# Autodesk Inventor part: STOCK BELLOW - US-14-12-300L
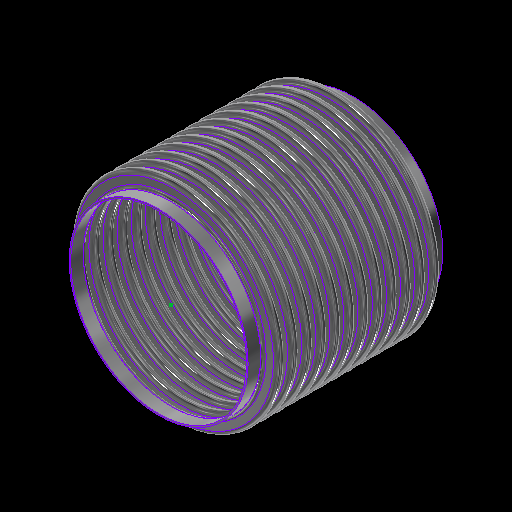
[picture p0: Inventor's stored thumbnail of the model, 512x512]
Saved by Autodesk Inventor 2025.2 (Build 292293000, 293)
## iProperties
Category: 16 GA (0.060 THICK)
RuleStatus: InUse
Created: 2024-01
Part Number: STOCK BELLOW - US-14-12-300L
Project: =STOCK BELLOWS: <Stock Number><SFILL>
Material: ASTM A240-304
Description: =STOCK BELLOWS: <Stock Number>, <SID_> I.D., <SOD_> O.D., <SPLY_> PLY, <Category>, <SNET_CONS> CONS.<PITCH_><STANGENT_> TANGENT<SFILL>
Document SubType Name: Sheet Metal
Designer: GS
Stock Number: U.S-14-12-300L
Surface Area: 22879.5 cm^2
Volume: 3455.43 cm^3
Sheet Metal Rule: Default
Appearance: STAINLESS STEEL
Mass: 27841.4 g
Density: 8.05729 g/cm^3
THK: 0.036
ID: 3.500
OD: 4.250
CONS_: 2
PITCH: 0.500
TANGENT: 0.500
BELLOWS_UPSET: 0.000
d79: 1.000
d82: 1.000
d83: 26.000
d84: 24.000
d174: 8
d214: 8
STHK_: 0.060
SID_: 14.000
SOD_: 16.500
SPITCH_: 1.125
STANGENT__: 1.000
SBELLOWS_UPSET_: 0.000
SDIFF_TAN: 1.000
d252: 2
d275: 2
d287: 0.050
d289: 0.500
d290: 0.000
SOD_NECK: 14 1/4
PLY: 1
PSET: 4.178
PBAR: 1.035
COUNTER: 1.500
NET_TUBE: 3.071
CONS: 2
S_CONS: 0
NET_CONS: 2
ID_M: 88.90 mm
OD_M: 107.95 mm
THK_M: 0.91 mm
ID_U: 3.500 in
OD_U: 4.250 in
THK_U: 0.036 in
TANGENT2: 0.500
TAN_TO_TAN: 1.000 in
d80: 2.571
d81: 10
SID: 2.375
SCONS_: 12
SPITCH: 0.250
STANGENT_: 1.000
SBELLOWS_UPSET: 0.000
SNET_CONS: 12
SS_CONS: 0
SCONS: 8
d190: 8
d191: 1
d192: 1
d193: 8
d194: 0
SIZE: 14.00
PRESSURE: 300
d230: 8
STANGENT: 4.000
SPLY_: 2
d233: 8
d234: 0
d263: 2
d265: 1
d268: 2
d269: 0
d286: 2
d288: 1
d291: 2
d292: 0
SREROLL: 0.750
BLETP: 1.000 ul
PRES_Copy: 85
MATTABLE: 20 GA (0.036 THICK)
PART_NUMBER: U.S-14-12-300L
PITCH_: =, <SPITCH_> PITCH,
CFILL: .
SFILL: .
MESH: ,
COMP: 2.32
EXT: 1.16
LAT: 0.68
ANG: 573
ASR: 5457
LSR: 10445
ANSR: 2769
PRES: 300
COMPM: 23.2
EXTM: 11.6
LATM: 6.80
ASRM: 955.684
PRESM: 20.684
LSRM: 1829.233
ANSRM: 484.935
TEMPMIN: 20
TEMPMAX: 800
TEMPMINM: -7
TEMPMAXM: 427
WEIGHTM: 27.841
WEIGHT: 61.380
Author: GS
Keywords: 20 GA (0.036 THICK)
Comments: =STOCK BELLOW - <STOCK NUMBER>
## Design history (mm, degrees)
sketch "Sketch2"
  geometry: L1 (0, -177.245)-(0, 562.856) reference; L2 (45.364, 0)-(44.45, 0); L3 (48.082, -2.718)-(50.343, -2.718); L4 (48.082, -3.632)-(50.343, -3.632); L5 (50.343, -9.982)-(48.082, -9.982); L6 (50.343, -9.068)-(48.082, -9.068); L7 (45.364, -12.7)-(44.45, -12.7); L8 (48.082, 0)-(48.082, -12.7); L9 (50.343, -6.35)-(53.975, -6.35); L10 (44.45, 0)-(44.45, -12.7); L11 (20.376, 102.841)-(20.376, 101.926); L12 (58.262, 457.127)-(58.262, 349.177); L13 (58.262, 444.427)-(58.262, 336.477); L14 (93.133, -58.817)-(93.133, -71.517); L15 (118.746, -66.401)-(118.746, -66.401); L16 (50.343, -9.068)-(50.343, -9.982); L17 (48.082, -9.068)-(48.082, -9.982); L18 (48.082, -9.525)-(50.343, -9.525); L19 (53.975, 0)-(53.975, -12.7); L20 (-50.343, -9.068)-(-50.343, -9.982); L21 (-50.343, -2.718)-(-48.082, -2.718); L22 (-50.343, -3.632)-(-48.082, -3.632); L23 (-48.082, -9.068)-(-50.343, -9.068); L24 (-50.343, -9.525)-(-48.082, -9.525); L25 (-48.082, -9.982)-(-50.343, -9.982); L26 (-48.082, -9.068)-(-48.082, -9.982); L27 (-44.45, 0.653)-(-44.45, -12.047); L28 (-48.082, -6.35)-(-44.45, -6.35); L29 (-50.343, 0.653)-(-50.343, -12.7); L30 (-53.061, 0)-(-53.975, 0); L31 (-53.975, 0)-(-53.975, -12.7); L32 (-53.061, -12.7)-(-53.975, -12.7); A1 r 2.718 centre (48.082, 0) between (45.364, 0) and (48.082, -2.718); A2 r 3.632 centre (48.082, 0) between (44.45, 0) and (48.082, -3.632); A3 r 3.632 centre (50.343, -6.35) between (50.343, -9.982) and (50.343, -2.718); A4 r 2.718 centre (50.343, -6.35) between (50.343, -9.068) and (50.343, -3.632); A5 r 2.718 centre (48.082, -12.7) between (48.082, -9.982) and (45.364, -12.7); A6 r 3.632 centre (48.082, -12.7) between (48.082, -9.068) and (44.45, -12.7); A7 r 3.175 centre (50.343, -6.35) between (50.343, -9.525) and (53.518, -6.35); A8 r 3.175 centre (48.082, -12.7) between (48.082, -9.525) and (44.907, -12.7); A9 r 2.718 centre (-50.343, -12.7) between (-50.343, -9.982) and (-53.061, -12.7); A10 r 2.718 centre (-48.082, -6.35) between (-48.082, -9.068) and (-48.082, -3.632); A11 r 3.175 centre (-48.082, -6.35) between (-48.082, -9.525) and (-44.907, -6.35); A12 r 3.632 centre (-48.082, -6.35) between (-48.082, -9.982) and (-48.082, -2.718); A13 r 3.175 centre (-50.343, -12.7) between (-50.343, -9.525) and (-53.518, -12.7); A14 r 3.632 centre (-50.343, -12.7) between (-50.343, -9.068) and (-53.975, -12.7); A15 r 2.718 centre (-50.343, 0) between (-53.061, 0) and (-50.343, -2.718); A16 r 3.632 centre (-50.343, 0) between (-53.975, 0) and (-50.343, -3.632); 10 further points
  constraints: 62 end point, 38 point on circle, 20 tangent, 16 centre point, 12 parallel, 9 midpoint, 7 vertical, 6 coincident, 6 concentric, 6 point on line, 4 equal radius, 4 perpendicular, 3 horizontal, 1 collinear, 1 horizontal alignment, 10 other
  dimensions: "THK" = 0.9144 distance of L11.start L11.end; "ID" = 88.9 distance of L11.end point (20.376, 13.026); "OD" = 107.95 distance of L12.start L12.end; "PITCH" = 12.7 distance of L12.start L13.start; "TANGENT" = 12.7 distance of L14.start L14.end; "BELLOWS_UPSET" = 0 distance of L15.start L15.end; "d43" = 88.9 diameter of L10 L1 (= ID); "d44" = 107.95 diameter of L9.end L1 (= OD); "d45" = 0.9144 distance between parallel lines of L5 L6 (computed from THK, PLY); "d46" = 3.6322 radius of A3 (computed from PITCH, THK, PLY); "UPSET_PITCH" = 12.7 distance of L2.end L7.end (derived); "SIDEWALL_ANGLE" = 360 deg dimension on L3 L9 (derived); "CON_GAP" = 5.4356 distance of point (48.082, -9.068) point (48.082, -3.632) (derived); "TAN1" = 4.98728 dimension on A8 (derived); "TAN2" = 4.98728 dimension on A7 (derived); "LEG1" = 2.2606 distance of L18.start L18.end (derived); "d278" = 0.9144 distance between parallel lines of L25 L23 (derived); "d279" = 3.6322 radius of A12 (derived); "d280" = 12.7 distance of L30.end L31.end (derived); "d281" = 360 deg dimension on L21 L28 (derived); "d282" = 5.4356 distance of point (-50.343, -9.068) point (-50.343, -3.632) (derived); "d283" = 4.98728 dimension on A13 (derived); "d284" = 4.98728 dimension on A11 (derived); "d285" = 2.2606 distance of L24.start L24.end (derived); "d293" = 88.9 diameter of L27 L1 (derived); "d294" = 107.95 diameter of L31 L1 (derived)
  node "Sketch Rectangular Pattern1" dims "d31" = 25.4, "ID" = 88.9
  node "Sketch Rectangular Pattern2" dims "d39" = 25.4, "PITCH" = 12.7
revolve "CONS" stored, may be unused: angle "d48" = 90 deg
node "BELLOW MIDPLANE"
pattern_linear "Rectangular Pattern2" dims "d52" = 12.7 (= UPSET_PITCH)
sketch "Sketch5"
  geometry: C1 r 45.364 at (0, 0) reference; C2 r 44.45 at (0, 0) reference
extrude "TANGENT" new body sketch "Sketch5" distance "d53" = 12.7 (= TANGENT); taper "d54" = 0 deg
revolve "SAMETAN" stored, may be unused: angle "d65" = 90 deg
revolve "DIFFTAN" stored, may be unused: angle "d70" = 90 deg
sketch "Sketch9"
  geometry: L1 (53.319, 0)-(-53.319, 0) reference; L2 (0, -17.78)-(0, 17.78) reference; L3 (38.085, 0)-(-38.085, 0); L4 (38.085, -11.906)-(38.085, 11.906); L5 (25.385, -11.906)-(25.385, 11.906); L6 (13.15, 11.906)-(13.15, -11.906); L7 (-25.385, -11.906)-(-25.385, 11.906); L8 (-38.085, -11.906)-(-38.085, 11.906); L9 (37.291, -11.906)-(37.291, 11.906); L10 (38.085, -11.906)-(37.291, -11.906); L11 (38.085, 11.906)-(37.291, 11.906); L12 (13.546, 11.906)-(12.753, 11.906); L13 (12.753, 11.906)-(12.753, -11.906); L14 (12.753, -11.906)-(13.546, -11.906); L15 (13.546, -11.906)-(13.546, 11.906); L16 (-13.546, 11.906)-(-13.546, -11.906); L17 (-13.15, 11.906)-(-13.15, -11.906); L18 (-13.546, -11.906)-(-12.753, -11.906); L19 (-12.753, -11.906)-(-12.753, 11.906); L20 (-12.753, 11.906)-(-13.546, 11.906); L21 (-38.085, -11.906)-(-37.291, -11.906); L22 (-37.291, -11.906)-(-37.291, 11.906); L23 (-37.291, 11.906)-(-38.085, 11.906); L24 (-38.085, 11.906)-(-38.085, -11.906); L25 (38.085, -0.397)-(-38.085, -0.397); L26 (-38.085, -0.397)-(-38.085, 0.397); L27 (-38.085, 0.397)-(38.085, 0.397); L28 (38.085, 0.397)-(38.085, -0.397); L29 (-38.085, 11.906)-(38.085, 11.906); L30 (38.085, 11.906)-(38.085, 12.7); L31 (38.085, 12.7)-(-38.085, 12.7); L32 (-38.085, 12.7)-(-38.085, 11.906); L33 (38.085, -11.906)-(-38.085, -11.906); L34 (-38.085, -11.906)-(-38.085, -12.7); L35 (-38.085, -12.7)-(38.085, -12.7); L36 (38.085, -12.7)-(38.085, -11.906); 30 further points
  constraints: 68 end point, 13 midpoint, 13 parallel, 8 horizontal, 7 perpendicular, 6 equal length, 3 point on line, 2 vertical, 14 other
  dimensions: "d115" = 23.8125 distance of L4.start L4.end (derived); "d116" = 12.7 distance between parallel lines of L4 L5 (derived); "d117" = 12.23516 distance between parallel lines of L5 L6 (derived); "d125" = 38.53427 distance between parallel lines of L7 L6 (derived); "d127" = 12.7 distance between parallel lines of L8 L7 (derived); "d128" = 24.93516 distance between parallel lines of L6 L4 (derived); "d130" = 76.16943 distance between parallel lines of L8 L4 (derived); "RULER_THK" = 0.79375 distance between parallel lines of L4 L9; "d135" = 0.79375 distance of L13.end L14.end (derived); "d138" = 26.29911 distance of L13.end L16.end (derived); "d143" = 0.79375 distance of L22.end L8.end (derived); "d144" = 0.79375 distance between parallel lines of L27 L25 (derived)
extrude "RULER" join sketch "Sketch9" distance "d149" = 0.79375 (derived); taper "d150" = 0 deg
extrude "BARS" join sketch "Sketch9" distance "d151" = 0.79375 (derived); taper "d152" = 0 deg
pattern_linear "Rectangular Pattern4" dims "d155" = 26.29911 (derived)
sketch "Sketch13"
  geometry: L1 (93.149, -52.467)-(93.149, -77.867); L2 (180.848, 0)-(177.8, 0); L3 (180.848, -28.575)-(177.8, -28.575); L4 (200.882, -22.955)-(186.468, -22.955); L5 (200.882, -19.907)-(186.468, -19.907); L6 (200.882, -14.287)-(209.55, -14.287); L7 (186.468, -5.62)-(200.882, -5.62); L8 (186.468, 0)-(186.468, -28.575); L9 (177.8, 0)-(177.8, -28.575); L10 (58.254, -77.331)-(58.254, -496.431); L11 (58.254, -105.906)-(58.254, -525.006); L12 (58.254, -163.056)-(58.254, -582.156); L13 (58.254, -191.631)-(58.254, -610.731); L14 (58.254, -220.206)-(58.254, -639.306); L15 (58.254, -248.781)-(58.254, -667.881); L16 (58.254, -277.356)-(58.254, -696.456); L17 (58.254, -134.481)-(58.254, -553.581); L18 (20.376, 103.45)-(20.376, 101.926); L19 (186.468, -8.668)-(200.882, -8.668); L20 (0, -856.437)-(0, 263.431) reference; L21 (-41.91, 0)-(251.46, 0) reference; A1 r 5.62 centre (186.468, 0) between (180.848, 0) and (186.468, -5.62); A2 r 5.62 centre (186.468, -28.575) between (186.468, -22.955) and (180.848, -28.575); A3 r 8.668 centre (186.468, -28.575) between (186.468, -19.907) and (177.8, -28.575); A4 r 5.62 centre (200.882, -14.287) between (200.882, -19.907) and (200.882, -8.668); A5 r 8.668 centre (200.882, -14.287) between (200.882, -22.955) and (200.882, -5.62); A6 r 8.668 centre (186.468, 0) between (177.8, 0) and (186.468, -8.668); 6 further points; 1 other entity
  constraints: 38 end point, 15 point on circle, 9 tangent, 6 centre point, 6 parallel, 5 vertical alignment, 4 point on line, 4 vertical, 3 coincident, 3 concentric, 2 collinear, 2 equal radius, 1 horizontal, 1 perpendicular, 23 other
  dimensions: "SBELLOWS_UPSET_" = 0 distance of point (118.762, -66.401) point (118.762, -66.401); "STOTAL_THK_BELLOW__" = 3.048 distance between parallel lines of L4 L5 (derived); "d224" = 8.66775 radius of A5 (derived); "d225" = 28.575 distance of L2.end L3.end (derived); "SSIDEWALL_ANGLE_" = 360 deg dimension on L7 L6 (derived); "SSCON_GAP_" = 11.2395 distance of point (186.468, -19.907) point (186.468, -8.668) (derived); "d235" = 355.6 diameter of L9 L20 (derived); "d236" = 419.1 diameter of L6.end L20 (derived)
  node "Sketch Rectangular Pattern4" dims "d228" = 25.4
  node "Sketch Rectangular Pattern5" dims "d229" = 25.4
revolve "SBELLOW" stored, may be unused: angle "d197" = 90 deg
pattern_linear "Rectangular Pattern5" dims "d204" = 28.575 (derived)
revolve "STANGENT" stored, may be unused: angle "d240" = 90 deg
revolve "SSAMETAN" stored, may be unused: angle "d241" = 90 deg
revolve "SDIFFTAN" stored, may be unused: angle "d246" = 90 deg
revolve "INVCON" stored, may be unused: angle "d295" = 90 deg
pattern_linear "Rectangular Pattern6" dims "d298" = 12.7 (derived)
revolve "INVTANGENT" stored, may be unused: angle "d302" = 90 deg
revolve "INVSAMETAN" stored, may be unused: angle "d307" = 90 deg
revolve "INVDIFFTAN" stored, may be unused: angle "d312" = 90 deg
sketch "ID BELLOW MOUNT CALC"
  geometry: L1 (44.45, 0)-(38.1, 0); L2 (38.1, 0)-(38.1, 12.7); L3 (38.1, 12.7)-(44.45, 12.7); L4 (44.45, 12.7)-(44.45, 0); L5 (36.513, 12.7)-(35.598, 12.7); L6 (35.598, 12.7)-(35.598, 0); L7 (35.598, 0)-(36.513, 0); L8 (36.513, 0)-(36.513, 12.7); L9 (0, -2.54)-(0, 15.24) reference; L10 (-8.89, 0)-(53.34, 0) reference; 1 further point
  constraints: 16 end point, 5 parallel, 2 collinear, 2 horizontal, 2 perpendicular
  dimensions: "d314" = 12.7 distance of L5.end L6.end (derived); "d315" = 0.9144 distance of L5.start L5.end (derived); "IG" = 1.5875 distance between parallel lines of L2 L8; "PIPE_OD" = 88.9 diameter of L4 L9; "PIPE_WALL" = 6.35 distance of L2.end L3.end; "ID_MT_BELLOW" = 71.1962 diameter of L6 L9 (derived)
revolve "CFILL" stored, may be unused: angle "d320" = 90 deg
pattern_linear "Rectangular Pattern7" dims "d323" = 12.7 (derived)
revolve "SFILL" stored, may be unused: angle "d324" = 90 deg
pattern_linear "Rectangular Pattern8" dims "d327" = 28.575 (derived)
node "STOCK BELLOW MIDPLANE"
node "BELLOW"
sketch "Sketch6"
  geometry: L1 (-12.7, 45.364)-(0, 45.364); L2 (0, 45.364)-(0, 44.45); L3 (0, 44.45)-(-12.7, 44.45); L4 (-12.7, 44.45)-(-12.7, 45.364); L5 (10.16, 0)-(-60.96, 0) reference; L6 (-38.1, -89.422)-(-38.1, 153.44) reference; 1 further point
  constraints: 8 end point, 2 parallel, 1 horizontal, 1 perpendicular
  dimensions: "d61" = 12.7 distance of L2.end L3.end (derived); "d62" = 0.9144 distance of L1.end L2.end (derived); "d63" = 88.9 diameter of L3 L5 (derived); "d64" = 25.4 distance between parallel lines of L4 L6 (derived)
sketch "Sketch12"
  geometry: 1 further point
sketch "Sketch14"
  geometry: L1 (-25.4, 180.848)-(0, 180.848); L2 (0, 180.848)-(0, 177.8); L3 (0, 177.8)-(-25.4, 177.8); L4 (-25.4, 177.8)-(-25.4, 180.848); L5 (5.08, 0)-(-30.48, 0) reference; L6 (0, -36.17)-(0, 217.018) reference; 1 further point
  constraints: 8 end point, 2 parallel, 1 collinear, 1 horizontal, 1 perpendicular
  dimensions: "d237" = 3.048 distance of L3.end L1.start (derived); "d238" = 355.6 diameter of L3 L5 (derived); "d239" = 25.4 distance of L1.start L1.end (derived); "SOD_NECK" = 361.696 diameter of L1 L5 (derived)
sketch "Sketch15"
  geometry: L1 (-36.17, 0)-(217.018, 0) reference; L2 (177.8, -342.9)-(180.848, -342.9); L3 (180.848, -342.9)-(180.848, -368.3); L4 (180.848, -368.3)-(177.8, -368.3); L5 (177.8, -368.3)-(177.8, -342.9); L6 (0, -444.5)-(0, 88.9) reference; 1 further point
  constraints: 8 end point, 2 parallel, 1 horizontal, 1 perpendicular
  dimensions: "d205" = 25.4 distance of L4.end L2.start (derived); "d206" = 3.048 distance of L3.end L4.end (derived); "d207" = 355.6 diameter of L5 L6 (derived); "d208" = 342.9 distance between parallel lines of L1 L2 (derived)
node "TANGENT_"
node "SAME_TAN"
sketch "Sketch8"
  geometry: L1 (45.364, -25.4)-(44.45, -25.4); L2 (44.45, -25.4)-(44.45, -38.1); L3 (44.45, -38.1)-(45.364, -38.1); L4 (45.364, -38.1)-(45.364, -25.4); L5 (0, -48.26)-(0, 22.86) reference; L6 (-89.422, 0)-(153.44, 0) reference; 1 further point
  constraints: 8 end point, 2 parallel, 1 horizontal, 1 perpendicular
  dimensions: "d66" = 88.9 diameter of L2 L5 (derived); "TOTAL_THK_BELLOW" = 0.9144 distance of L2.end L3.end (derived); "d68" = 25.4 distance between parallel lines of L1 L6 (derived); "d69" = 12.7 distance of L1.end L2.end (derived)
node "DIFF_TAN"
node "Sketch Rectangular Pattern3" dims "d138" = 26.29911 (derived), "d141" = 25.4
node "SBELLOW_"
node "STANGENT_"
node "SSAME_TAN"
sketch "Sketch16"
  geometry: L1 (180.848, -342.9)-(177.8, -342.9); L2 (177.8, -342.9)-(177.8, -368.3); L3 (177.8, -368.3)-(180.848, -368.3); L4 (180.848, -368.3)-(180.848, -342.9); L5 (0, -444.5)-(0, 88.9) reference; L6 (-36.17, 0)-(217.018, 0) reference; 1 further point
  constraints: 8 end point, 2 parallel, 1 horizontal, 1 perpendicular
  dimensions: "SDIFF_TAN" = 25.4 distance of L3.end L1.start; "d243" = 3.048 distance of L2.end L3.end (derived); "d244" = 342.9 distance between parallel lines of L1 L6 (derived); "d245" = 355.6 diameter of L2 L5 (derived)
node "SDIFF_TAN"
body "Solid15"
sketch "Sketch17"
  geometry: L1 (53.975, 12.7)-(53.061, 12.7); L2 (53.061, 12.7)-(53.061, 0); L3 (53.061, 0)-(53.975, 0); L4 (53.975, 0)-(53.975, 12.7); L5 (0, -2.54)-(0, 15.24) reference; L6 (-10.795, 0)-(64.77, 0) reference; 2 further points
  constraints: 8 end point, 2 parallel, 1 horizontal, 1 midpoint, 1 perpendicular, 1 point on line
  dimensions: "INVTANGENT" = 12.7 distance of L3.end L1.start (derived); "d300" = 0.9144 distance of L1.start L1.end (derived); "d301" = 107.95 diameter of L4 L5 (derived)
body "Solid16"
sketch "Sketch18"
  geometry: L1 (53.975, -25.4)-(53.061, -25.4); L2 (53.061, -25.4)-(53.061, -38.1); L3 (53.061, -38.1)-(53.975, -38.1); L4 (53.975, -38.1)-(53.975, -25.4); L5 (-10.795, 0)-(64.77, 0) reference; L6 (0, -48.26)-(0, 22.86) reference; 1 further point
  constraints: 8 end point, 2 parallel, 1 horizontal, 1 perpendicular
  dimensions: "d303" = 25.4 distance between parallel lines of L1 L5 (derived); "d304" = 12.7 distance of L3.end L1.start (derived); "d305" = 0.9144 distance of L2.end L3.end (derived); "d306" = 107.95 diameter of L4 L6 (derived)
body "Solid17"
sketch "Sketch19"
  geometry: L1 (53.975, -25.4)-(53.061, -25.4); L2 (53.061, -25.4)-(53.061, -38.1); L3 (53.061, -38.1)-(53.975, -38.1); L4 (53.975, -38.1)-(53.975, -25.4); L5 (0, -48.26)-(0, 22.86) reference; L6 (-10.795, 0)-(64.77, 0) reference; 1 further point
  constraints: 8 end point, 2 parallel, 1 horizontal, 1 perpendicular
  dimensions: "d308" = 12.7 distance of L1.end L2.end (derived); "d309" = 107.95 diameter of L4 L5 (derived); "d310" = 0.9144 distance of L2.end L3.end (derived); "d311" = 25.4 distance between parallel lines of L1 L6 (derived)
body "Solid18"
body "Solid19"
body "Solid20"
other parameters: "BMPL" = -171.45, "PSET" = 106.1212 (computed from OD, THK, PLY) [user parameter], "PBAR" = 26.29911 (= 0.570796 x PITCH + OD - ID) [user parameter; used in 1 equation term], "COUNTER" = 15 [user parameter], "NET_TUBE" = 77.99823 (computed from CONS_, PBAR, TANGENT) [user parameter], "S_CONS" = 0 [user parameter; used in 1 equation term], "ID_M" = 88.9 (= ID) [user parameter], "OD_M" = 107.95 (= OD) [user parameter], "THK_M" = 0.9144 (= THK) [user parameter], "ID_U" = 88.9 (= ID) [user parameter], "OD_U" = 107.95 (= OD) [user parameter], "THK_U" = 0.9144 (= THK) [user parameter], "D_UNITS" = 0 [user parameter], "TANGENT2" = 12.7 [user parameter], "TAN_TO_TAN" = 25.4 [user parameter], "OD_NECK" = 90.7288 [user parameter], "d79" = 25.4, "d80" = 65.29823 [user parameter], "d82" = 25.4, "d83" = 660.4, "d84" = 609.6, "sa_0" = 4, "FRAME_THK" = 0.79375 [user parameter], "CON_FLAT" = 12.23516 [user parameter], "SID" = 60.325 [user parameter], "SPITCH" = 6.35 [user parameter], "STANGENT_" = 25.4 [user parameter], "SBELLOWS_UPSET" = 0 [user parameter], "SS_CONS" = 0 [user parameter], "STAN_TO_TAN_" = 342.9 [user parameter], "d100" = 3.048 [user parameter], "d191" = 25.4 [user parameter], "d194" = 0 [user parameter], "STANGENT" = 101.6 [user parameter], "d234" = 0 [user parameter], "SUPSET_PITCH_" = 28.575 [user parameter], "d269" = 0 [user parameter], "d287" = 1.27, "d289" = 12.7, "d290" = 0, "d292" = 0 [user parameter], "Thickness" = 3.048 (derived), "KFactor" = 4.4, "BendRadius" = 3.048 (derived), "BendReliefWidth" = 3.048 (derived), "BendReliefDepth" = 1.524 (derived), "CornerReliefSize" = 12.192 (derived), "SeamGap" = 0.00508, "MinimumRemnant" = 6.096 (derived), "TransitionRadius" = 3.048 (derived), "JacobiRadiusSize" = 3.048 (derived), "GapSize" = 3.048 (derived), "SREROLL" = 19.05 [user parameter], "CUR_STK_PITCH" = 28.575 [user parameter], "d328" = -171.45 (derived), "ASR" = 54570 [user parameter], "LSR" = 104450 [user parameter], "ANSR" = 27690 [user parameter], "BLETP" = 1 [user parameter], "ASRM" = 9556.8441 [user parameter], "PRESM" = 206.83949 [user parameter], "LSRM" = 18292.3285 [user parameter], "ANSRM" = 4849.3497 [user parameter], "TEMPMIN" = 2664.83333 [user parameter], "TEMPMAX" = 6998.16667 [user parameter], "TEMPMINM" = 2664.83333 [user parameter], "TEMPMAXM" = 6998.16667 [user parameter], "WEIGHT" = 278.41415 [user parameter], "WEIGHTM" = 0.27841 [user parameter]
